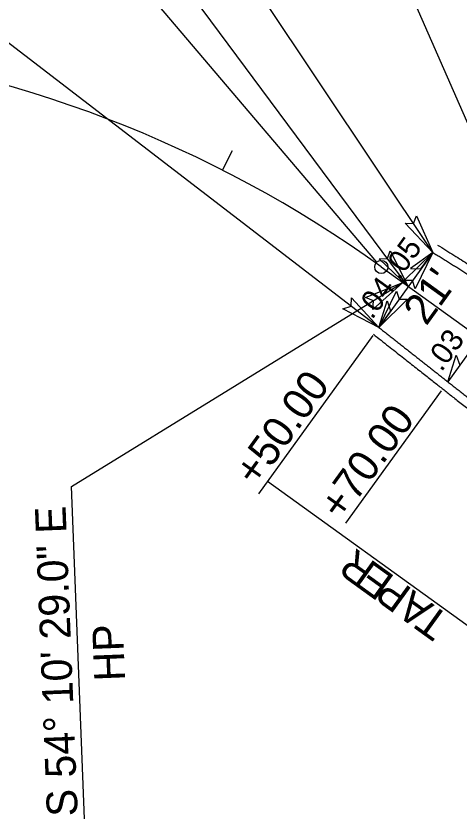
# Model space of a CAD drawing. Extents: x 1627861 to 1629601, y 761281 to 766239.
# Drawn here: x 1628159.8 to 1628260.9, y 764220.8 to 764403.8 of the extents above; entities that cross this region are included whole.
import ezdxf

# ---------------------------------------------------------------- set-up
doc = ezdxf.new("R2010")
doc.units = 0
for name, color, linetype in [('Cogo Default Point CELL', 7, 'Continuous'), ('Exist Hydro Jurisdictional Stream or Body of Water', 7, 'Continuous'), ('Exist Other Culture Sign Leader', 7, 'Continuous'), ('Exist Property Tie Line Text', 7, 'Continuous'), ('Exist Right of Way Line Leader', 7, 'Continuous'), ('Exist Right of Way Monument Text', 7, 'Continuous'), ('Exist Utilities Gas Meter CELL', 7, 'Continuous'), ('Exist Utilities Gas Meter Cogo Elevation', 7, 'Continuous'), ('Exist Utilities Gas Meter Cogo Number', 7, 'Continuous'), ('Exist Utilities Power UG Cable SUE LOS B Cogo Point CELL', 7, 'Continuous'), ('Exist Utilities Water UG Line SUE LOS B Cogo Number', 7, 'Continuous'), ('Scratch_Level_0', 7, 'Continuous'), ('Typical Terminator CELL', 7, 'Continuous')]:
    doc.layers.add(name, color=color, linetype=linetype)

msp = doc.modelspace()

# ---------------------------------------------------------------- linework, layer by layer
at = {"layer": 'Exist Hydro Jurisdictional Stream or Body of Water'}
msp.add_arc((1628081.99, 764123.59), 275, 54.1747, 83.8451, dxfattribs=at)
at = {"layer": 'Exist Property Tie Line Text'}
msp.add_line((1628206.8, 764368.64), (1628209.07, 764373.1), dxfattribs=at)
at = {"layer": 'Exist Right of Way Line Leader'}
for p, q in [((1628292.11, 764311.82), (1628245.8, 764417.86)), ((1628241.92, 764347.65), (1628186.59, 764412.91)), ((1628172.42, 764296.56), (1628247.88, 764343.01)), ((1628175.41, 764220.75), (1628172.42, 764296.56))]:
    msp.add_line(p, q, dxfattribs=at)
msp.add_circle((1628242.96, 764346.57), 1.5, dxfattribs=at)
at = {"layer": 'Exist Right of Way Monument Text'}
for points in [[(1628254.71, 764349.88), (1628255.18, 764349.58), (1628255.65, 764349.29), (1628256.12, 764348.99), (1628256.59, 764348.7), (1628257.06, 764348.4), (1628257.53, 764348.11), (1628258.01, 764347.82), (1628258.48, 764347.52), (1628258.95, 764347.23), (1628259.42, 764346.93), (1628259.89, 764346.64), (1628260.36, 764346.34), (1628260.83, 764346.05), (1628261.3, 764345.75), (1628261.77, 764345.46), (1628262.24, 764345.16), (1628262.71, 764344.87), (1628263.18, 764344.58), (1628263.65, 764344.28), (1628264.12, 764343.99), (1628264.6, 764343.69), (1628265.07, 764343.4), (1628265.54, 764343.1), (1628266.01, 764342.81), (1628266.48, 764342.51), (1628266.95, 764342.22), (1628267.42, 764341.92), (1628267.89, 764341.63), (1628268.36, 764341.34), (1628268.83, 764341.04), (1628269.3, 764340.75), (1628269.77, 764340.45), (1628270.24, 764340.16), (1628270.71, 764339.86), (1628271.19, 764339.57), (1628271.66, 764339.27), (1628272.13, 764338.98), (1628272.6, 764338.68), (1628273.07, 764338.39), (1628273.54, 764338.1), (1628274.01, 764337.8), (1628274.48, 764337.51), (1628274.95, 764337.21), (1628275.42, 764336.92), (1628275.89, 764336.62), (1628276.36, 764336.33), (1628276.83, 764336.03), (1628277.3, 764335.74), (1628277.78, 764335.45), (1628278.25, 764335.15), (1628278.72, 764334.86), (1628279.19, 764334.56), (1628279.66, 764334.27), (1628280.13, 764333.97), (1628280.6, 764333.68), (1628281.07, 764333.38), (1628281.54, 764333.09), (1628282.01, 764332.79), (1628282.48, 764332.5), (1628282.95, 764332.21), (1628283.42, 764331.91), (1628283.9, 764331.62), (1628284.37, 764331.32), (1628284.84, 764331.03), (1628285.31, 764330.73), (1628285.78, 764330.44), (1628286.25, 764330.14), (1628286.72, 764329.85), (1628287.19, 764329.55), (1628287.66, 764329.26), (1628288.13, 764328.97), (1628288.6, 764328.67), (1628289.07, 764328.38), (1628289.54, 764328.08)], [(1628242.39, 764332.8), (1628242.82, 764332.46), (1628243.26, 764332.12), (1628243.69, 764331.77), (1628244.13, 764331.43), (1628244.56, 764331.09), (1628245, 764330.74), (1628245.43, 764330.4), (1628245.87, 764330.06), (1628246.3, 764329.71), (1628246.74, 764329.37), (1628247.17, 764329.03), (1628247.61, 764328.68), (1628248.05, 764328.34), (1628248.48, 764327.99), (1628248.92, 764327.65), (1628249.35, 764327.31), (1628249.79, 764326.96), (1628250.22, 764326.62), (1628250.66, 764326.28), (1628251.09, 764325.93), (1628251.53, 764325.59), (1628251.96, 764325.25), (1628252.4, 764324.9), (1628252.83, 764324.56), (1628253.27, 764324.22), (1628253.7, 764323.87), (1628254.14, 764323.53), (1628254.58, 764323.19), (1628255.01, 764322.84), (1628255.45, 764322.5), (1628255.88, 764322.16), (1628256.32, 764321.81), (1628256.75, 764321.47), (1628257.19, 764321.12), (1628257.62, 764320.78), (1628258.06, 764320.44), (1628258.49, 764320.09), (1628258.93, 764319.75), (1628259.36, 764319.41), (1628259.8, 764319.06), (1628260.24, 764318.72), (1628260.67, 764318.38), (1628261.11, 764318.03), (1628261.54, 764317.69), (1628261.98, 764317.35), (1628262.41, 764317), (1628262.85, 764316.66), (1628263.28, 764316.32), (1628263.72, 764315.97), (1628264.15, 764315.63), (1628264.59, 764315.28), (1628265.02, 764314.94), (1628265.46, 764314.6), (1628265.89, 764314.25), (1628266.33, 764313.91), (1628266.77, 764313.57), (1628267.2, 764313.22), (1628267.64, 764312.88), (1628268.07, 764312.54), (1628268.51, 764312.19), (1628268.94, 764311.85), (1628269.38, 764311.51), (1628269.81, 764311.16), (1628270.25, 764310.82), (1628270.68, 764310.48), (1628271.12, 764310.13), (1628271.55, 764309.79), (1628271.99, 764309.44), (1628272.43, 764309.1), (1628272.86, 764308.76), (1628273.3, 764308.41), (1628273.73, 764308.07), (1628274.17, 764307.73), (1628274.6, 764307.38)]]:
    msp.add_spline(points, degree=3, dxfattribs=at)
at = {"layer": 'Exist Utilities Gas Meter CELL'}
msp.add_line((1628242.96, 764346.57), (1628292.87, 764310.53), dxfattribs=at)
msp.add_arc((1628081.99, 764123.59), 275, 54.1747, 83.8451, dxfattribs=at)
at = {"layer": 'Exist Utilities Gas Meter Cogo Elevation'}
for points in [[(1628255.77, 764351.57), (1628267.38, 764344.31), (1628278.99, 764337.04), (1628290.6, 764329.78)], [(1628241.15, 764331.23), (1628251.89, 764322.76), (1628262.62, 764314.29), (1628273.36, 764305.81)]]:
    msp.add_open_spline(points, degree=2, dxfattribs=at)
at = {"layer": 'Exist Utilities Gas Meter Cogo Number'}
for points in [[(1628251.01, 764358.22), (1628254.71, 764349.88), (1628248.36, 764356.52), (1628250.33, 764356.45)], [(1628245, 764350.27), (1628249.11, 764342.12), (1628242.44, 764348.44), (1628244.41, 764348.47)], [(1628248.19, 764343.49), (1628254.71, 764349.88), (1628250.71, 764341.6), (1628250.09, 764343.47)], [(1628239.4, 764339.61), (1628247.88, 764343.01), (1628241.01, 764336.9), (1628241.15, 764338.87)], [(1628248.91, 764339.19), (1628242.39, 764332.8), (1628246.39, 764341.08), (1628247.01, 764339.21)], [(1628236.19, 764339.52), (1628242.39, 764332.8), (1628234.24, 764337.05), (1628236.12, 764337.62)]]:
    msp.add_lwpolyline(points, close=True, dxfattribs=at)
at = {"layer": 'Exist Utilities Water UG Line SUE LOS B Cogo Number'}
for p, q in [((1628254.71, 764349.88), (1628242.39, 764332.8)), ((1628271.7, 764339.25), (1628258.1, 764320.4))]:
    msp.add_line(p, q, dxfattribs=at)
at = {"layer": 'Scratch_Level_0'}
for p, q in [((1628242.39, 764332.8), (1628088.56, 764451.03)), ((1628249.11, 764342.12), (1628196.93, 764412.48)), ((1628254.71, 764349.88), (1628215.27, 764409.02)), ((1628254.71, 764349.88), (1628242.39, 764332.8)), ((1628241.04, 764330.95), (1628214.97, 764294.83)), ((1628256.59, 764318.31), (1628234.82, 764288.15)), ((1628217.06, 764297.73), (1628260.82, 764266.14))]:
    msp.add_line(p, q, dxfattribs=at)
msp.add_arc((1628322.14, 764351.07), 104.75, 234.1747, 264.4018, dxfattribs=at)
at = {"layer": 'Typical Terminator CELL'}
for points in [[(1628254.71, 764349.88), (1628249.58, 764346.18), (1628252, 764346.13)], [(1628242.39, 764332.8), (1628244.28, 764338.84), (1628245.09, 764336.55)], [(1628258.1, 764320.4), (1628259.99, 764326.44), (1628260.81, 764324.15)]]:
    msp.add_lwpolyline(points, close=True, dxfattribs=at)

# ---------------------------------------------------------------- texts
at = {"layer": 'Cogo Default Point CELL'}
msp.add_text('S 54%%d 10\' 29.0" E', height=7, rotation=92.2582, dxfattribs=at).set_placement((1628173.86, 764221.44))
at = {"layer": 'Exist Other Culture Sign Leader'}
msp.add_text('HP', height=7, rotation=92.2582, dxfattribs=at).set_placement((1628184.63, 764252.27))
at = {"layer": 'Exist Utilities Power UG Cable SUE LOS B Cogo Point CELL'}
for s, rotation, p in [("21'", 54.1747, (1628253.19, 764332.95)), ('+50.00', 54.1747, (1628214.56, 764296.18)), ('+70.00', 54.1747, (1628233.93, 764288.45)), ('R', 144.1747, (1628242.34, 764278.73)), ('E', 144.1747, (1628246.29, 764275.87)), ('P', 144.1747, (1628250.25, 764273.02)), ('A', 144.1747, (1628255.17, 764269.47)), ('T', 144.1747, (1628258.95, 764266.73))]:
    msp.add_text(s, height=7, rotation=rotation, dxfattribs=at).set_placement(p)
at = {"layer": 'Exist Utilities Water UG Line SUE LOS B Cogo Number'}
for s, p in [('.05', (1628247, 764343.46)), ('.04', (1628240.88, 764334.4)), ('.03', (1628256.67, 764322.49))]:
    msp.add_text(s, height=5, rotation=54.1747, dxfattribs=at).set_placement(p)

doc.saveas('drawing.dxf')
